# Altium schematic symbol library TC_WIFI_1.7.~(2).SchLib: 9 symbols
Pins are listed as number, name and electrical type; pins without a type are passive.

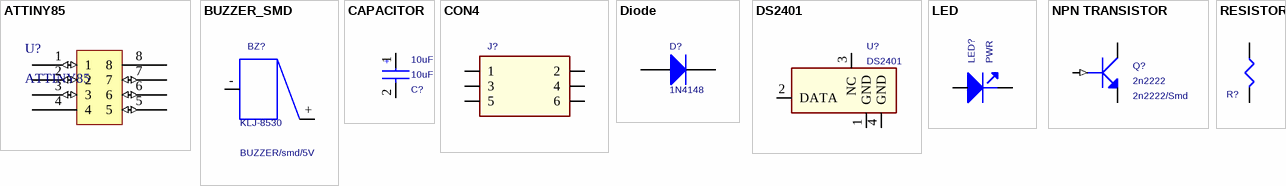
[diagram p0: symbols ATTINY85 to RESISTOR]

## ATTINY85
designator U?
pins: 1 (io), 2 (io), 3 (io), 4 (power), 5 (io), 6 (io), 7 (io), 8 (power)

## BUZZER_SMD
designator BZ?, comment KLJ-8530  PART: BUZZER/smd/5V
Buzzer
footprint BUZZER SMD
pins: +, -

## CAPACITOR
designator C?, comment 10uF  PART: 10uF/Smd
Capacitor
footprint 0805T
pins: 1 +, 2 -

## CON4
designator J?
Header 2*3 Male
footprint IDC6
pins: 1, 2, 3, 4, 5, 6

## Diode
designator D?, comment 1N4148
Diode
footprint 0805-D
simulation model DIODE (Diode)
signal-integrity model Diode
pins: A, K

## DS2401
designator U?
Silicon Serial Number
footprint DS2401
pins: 1 GND, 2 DATA, 3 NC, 4 GND

## LED
designator LED?, comment PWR
LED
footprint 0805-D
pins: 1, 2

## NPN TRANSISTOR
designator Q?, comment 2n2222  PART: 2n2222/Smd
NPN Transistor
footprint SOT23_3
pins: 1 (in), 2, 3

## RESISTOR
designator R?
Resistor; PART: 270K/Smd
footprint 0805R
pins: 1, 2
